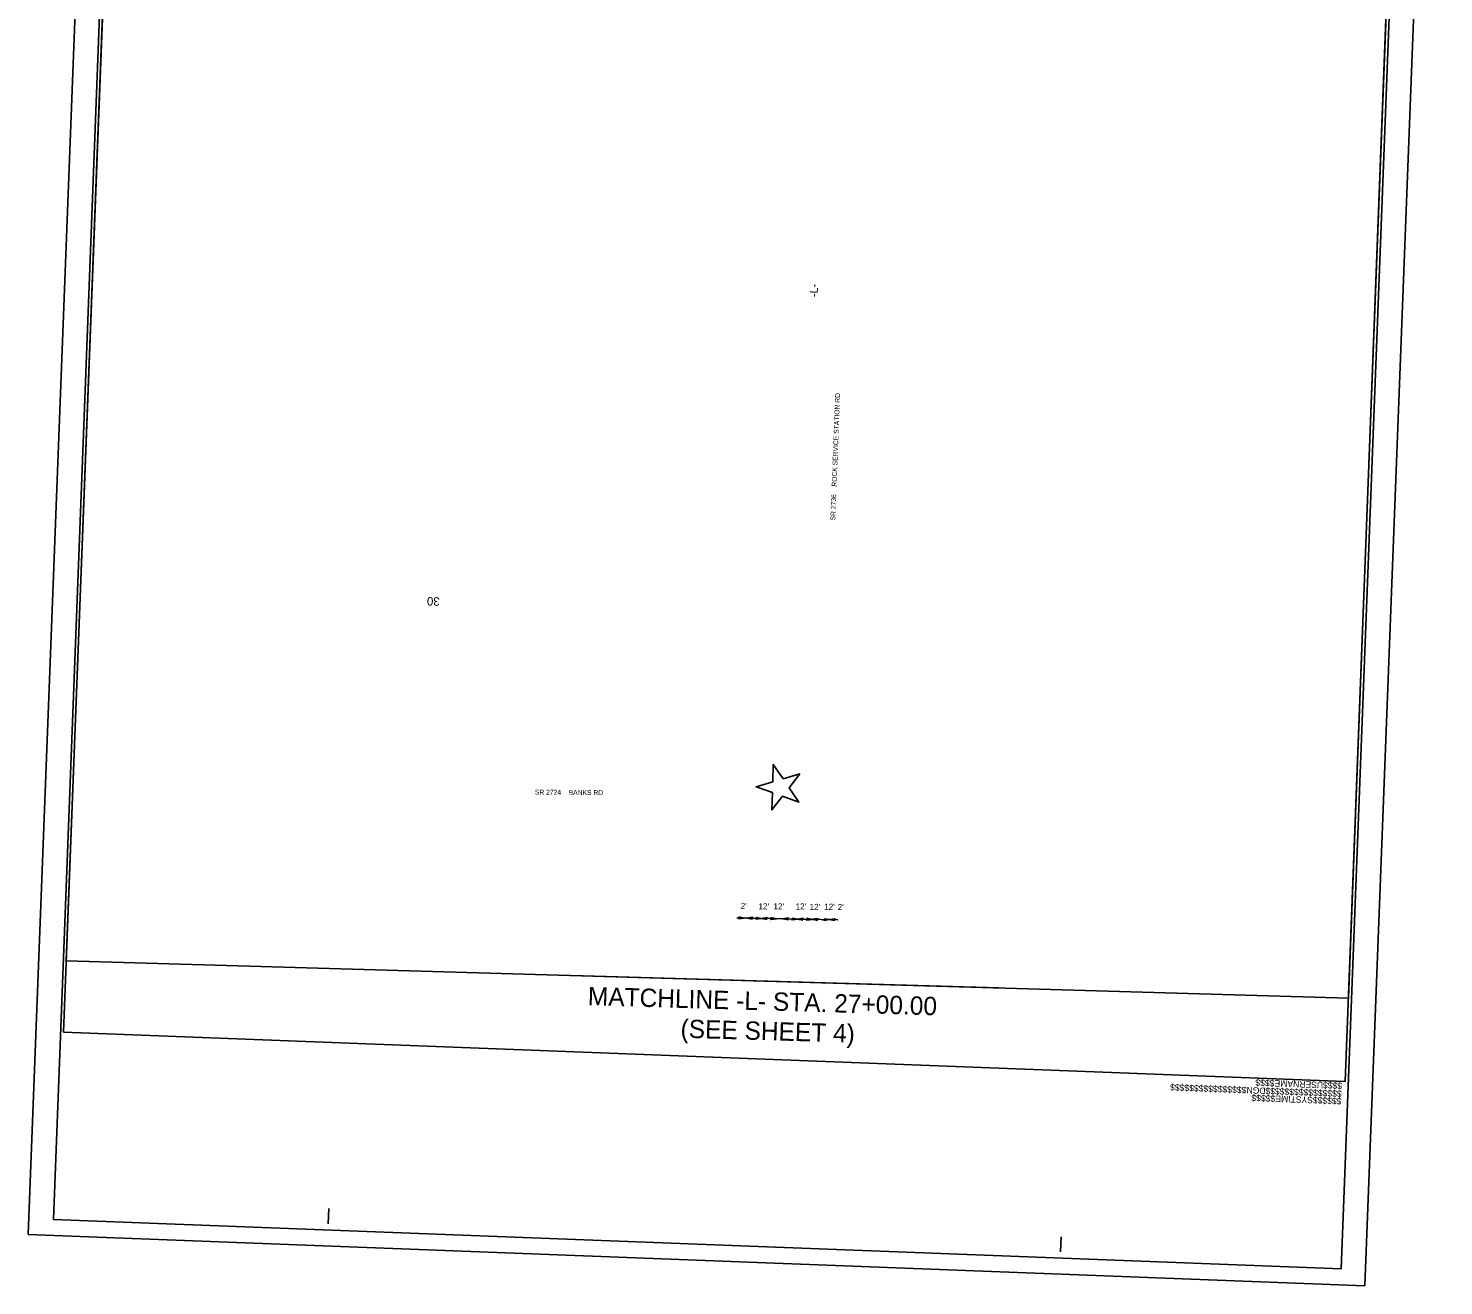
# Model space of a CAD drawing. Extents: x 2097098 to 2098257, y 686470 to 688528.
# Drawn here: x 2097098 to 2098257, y 686470 to 687499 of the extents above; entities that cross this region are included whole.
import ezdxf

# ---------------------------------------------------------------- set-up
doc = ezdxf.new("R2010")
doc.units = 0
for name, color, linetype in [('Default', 7, 'Continuous'), ('Matchline', 7, 'Continuous'), ('Matchline Text', 7, 'Continuous'), ('Prop Horizontal Alignment Station Label', 7, 'Continuous'), ('Prop Horizontal Alignment Tick Label', 7, 'Continuous'), ('Sheet Layout Plan Border', 7, 'Continuous'), ('Sheet Plan CELL', 7, 'Continuous'), ('Sheet Plot Border Inside CELL', 7, 'Continuous'), ('Sheet Plot Border Outside CELL', 7, 'Continuous'), ('Text', 7, 'Continuous')]:
    doc.layers.add(name, color=color, linetype=linetype)

msp = doc.modelspace()

# ---------------------------------------------------------------- linework, layer by layer
at = {"layer": 'Default'}
msp.add_line((2097761.1, 686769.5), (2097678.6, 686771), dxfattribs=at)
msp.add_lwpolyline([(2097716.4, 686884.9), (2097708.3, 686896.6), (2097707.9, 686882.4), (2097694.3, 686878.4), (2097707.7, 686873.6), (2097707.3, 686859.4), (2097716, 686870.6), (2097729.4, 686865.9), (2097721.3, 686877.6), (2097730, 686888.9), (2097716.4, 686884.9)], dxfattribs=at)
for points in [[(2097680.3, 686771.8), (2097684.7, 686770.9), (2097680.2, 686770.2), (2097680.8, 686771)], [(2097691.3, 686770), (2097686.8, 686770.9), (2097691.4, 686771.6), (2097690.8, 686770.8)], [(2097694.2, 686771.5), (2097698.7, 686770.6), (2097694.2, 686769.9), (2097694.8, 686770.7)], [(2097703.2, 686769.8), (2097698.7, 686770.6), (2097703.3, 686771.4), (2097702.7, 686770.6)], [(2097706.4, 686771.3), (2097710.9, 686770.4), (2097706.3, 686769.7), (2097706.9, 686770.5)], [(2097720.7, 686769.5), (2097716.2, 686770.3), (2097720.8, 686771), (2097720.2, 686770.2)], [(2097723.9, 686770.9), (2097728.4, 686770.1), (2097723.8, 686769.4), (2097724.4, 686770.1)], [(2097732.7, 686769.2), (2097728.2, 686770.1), (2097732.8, 686770.8), (2097732.2, 686770)], [(2097735.9, 686770.7), (2097740.4, 686769.8), (2097735.8, 686769.1), (2097736.4, 686769.9)], [(2097744.7, 686769), (2097740.2, 686769.9), (2097744.8, 686770.6), (2097744.2, 686769.8)], [(2097749.9, 686770.4), (2097754.4, 686769.6), (2097749.8, 686768.9), (2097750.4, 686769.7)], [(2097758.7, 686768.8), (2097754.2, 686769.6), (2097758.8, 686770.3), (2097758.2, 686769.5)]]:
    msp.add_lwpolyline(points, close=True, dxfattribs=at)
at = {"layer": 'Matchline'}
msp.add_line((2097543.1, 686723.9), (2097892.9, 686713.8), dxfattribs=at)
at = {"layer": 'Sheet Layout Plan Border'}
msp.add_lwpolyline([(2098218.4, 687728.9), (2098179.2, 686705.4), (2097129.6, 686735.9), (2097169.5, 687776.6), (2097171.5, 687828.5), (2097176.8, 687967), (2097416.7, 687957.8), (2097421.5, 688081.2), (2098143.3, 688053.5), (2098131, 687732.3)], close=True, dxfattribs=at)
at = {"layer": 'Sheet Plan CELL'}
for p, q in [((2097184.8, 688176.4), (2097127.3, 686677.5)), ((2098176.6, 686637.2), (2098234.1, 688136.1)), ((2097127.3, 686677.5), (2098176.6, 686637.2)), ((2098176.6, 686637.2), (2098176.6, 686637.2)), ((2097344, 686520.6), (2097344.5, 686533.1)), ((2097943.6, 686497.6), (2097944.1, 686510.1))]:
    msp.add_line(p, q, dxfattribs=at)
at = {"layer": 'Sheet Plot Border Inside CELL'}
msp.add_lwpolyline([(2098173.2, 686483.8), (2098237, 688148.5), (2097182.8, 688188.9), (2097119, 686524.2)], close=True, dxfattribs=at)
at = {"layer": 'Sheet Plot Border Outside CELL'}
msp.add_lwpolyline([(2098192.7, 686470), (2098257.2, 688152.2), (2097163, 688194.2), (2097098.5, 686512)], close=True, dxfattribs=at)

# ---------------------------------------------------------------- texts
at = {"layer": 'Matchline Text'}
for s, p in [('MATCHLINE -L- STA. 27+00.00', (2097556.4, 686699.6)), ('(SEE SHEET 4)', (2097632.3, 686673))]:
    msp.add_text(s, height=15, rotation=358.3348, dxfattribs=at).set_placement(p)
at = {"layer": 'Prop Horizontal Alignment Station Label'}
msp.add_text('-L-', height=6.64, rotation=88.3348, dxfattribs=at).set_placement((2097744.7, 687279.1))
at = {"layer": 'Prop Horizontal Alignment Tick Label'}
msp.add_text('30', height=7, rotation=177.8037, dxfattribs=at).set_placement((2097435.4, 687033.4))
at = {"layer": 'Sheet Plan CELL'}
for s, p in [('$$$$$$$$$$$$$$$$DGN$$$$$$$$$$$$$$$$', (2098173.9, 686629.7)), ('$$$$USERNAME$$$$', (2098174.2, 686636.2)), ('$$$$$$SYSTIME$$$$$', (2098173.7, 686623.6))]:
    msp.add_text(s, height=5.25, rotation=177.8037, dxfattribs=at).set_placement(p)
at = {"layer": 'Text'}
for s, height, rotation, p in [('SR 2736    ROCK SERVICE STATION RD   ', 4, 87.8037, (2097759.1, 687096.3)), ('SR 2724    BANKS RD   ', 4, 359.5717, (2097513.2, 686872)), ("2'", 5, 0.223, (2097681.7, 686778.3)), ("12'", 5, 0.223, (2097696.2, 686778)), ("12'", 5, 0.223, (2097708.5, 686778)), ("12'", 5, 0.223, (2097726.6, 686777.9)), ("12'", 5, 0.223, (2097738, 686777.5)), ("12'", 5, 0.223, (2097750, 686777.6)), ("2'", 5, 0.223, (2097761.1, 686777.4))]:
    msp.add_text(s, height=height, rotation=rotation, dxfattribs=at).set_placement(p)

doc.saveas('drawing.dxf')
